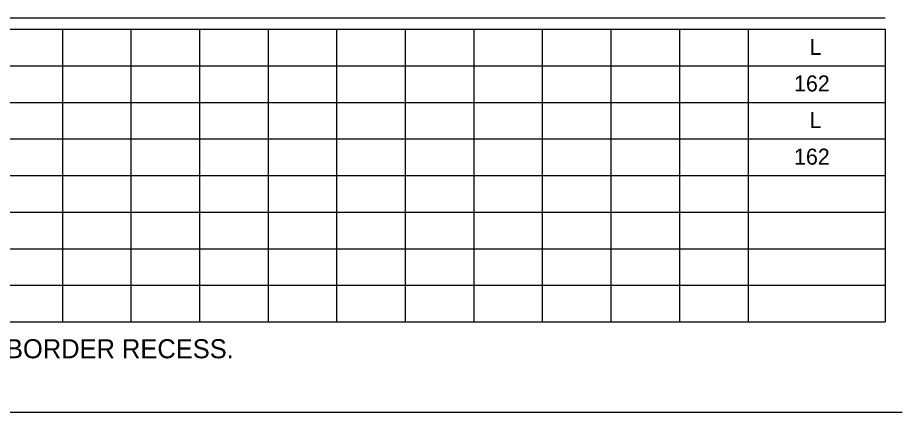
# Model space of a CAD drawing. Extents: x 10268312 to 10268472, y 2142583 to 2142688.
# Drawn here: x 10268433.03 to 10268471.73, y 2142640.28 to 2142657.53 of the extents above; entities that cross this region are included whole.
import ezdxf

# ---------------------------------------------------------------- set-up
doc = ezdxf.new("R2010")
doc.units = 0
for name, color, linetype in [('SheetBorder_dp', 7, 'Continuous'), ('SumBoxLines_dp', 7, 'Continuous'), ('SumBoxLinesMin_dp', 7, 'Continuous'), ('TextLabel', 7, 'Continuous'), ('TextNotes', 7, 'Continuous')]:
    doc.layers.add(name, color=color, linetype=linetype)

msp = doc.modelspace()

# ---------------------------------------------------------------- linework, layer by layer
at = {"layer": 'SheetBorder_dp'}
msp.add_line((10268317.73, 2142640.282), (10268471.73, 2142640.282), dxfattribs=at)
at = {"layer": 'SumBoxLines_dp'}
for p, q in [((10268418.73, 2142657.532), (10268470.98, 2142657.532)), ((10268395.48, 2142657.032), (10268470.98, 2142657.032)), ((10268434.98, 2142657.032), (10268434.98, 2142655.432)), ((10268437.98, 2142657.032), (10268437.98, 2142655.432)), ((10268440.98, 2142657.032), (10268440.98, 2142653.832)), ((10268443.98, 2142657.032), (10268443.98, 2142653.832)), ((10268446.98, 2142657.032), (10268446.98, 2142655.432)), ((10268449.98, 2142657.032), (10268449.98, 2142655.432)), ((10268452.98, 2142657.032), (10268452.98, 2142655.432)), ((10268455.98, 2142657.032), (10268455.98, 2142655.432)), ((10268458.98, 2142657.032), (10268458.98, 2142655.432)), ((10268461.98, 2142657.032), (10268461.98, 2142655.432)), ((10268464.98, 2142657.032), (10268464.98, 2142655.432)), ((10268470.98, 2142657.032), (10268470.98, 2142644.232)), ((10268434.98, 2142655.432), (10268434.98, 2142649.032)), ((10268437.98, 2142655.432), (10268437.98, 2142647.432)), ((10268440.98, 2142655.432), (10268440.98, 2142647.432)), ((10268443.98, 2142655.432), (10268443.98, 2142649.032)), ((10268446.98, 2142655.432), (10268446.98, 2142649.032)), ((10268449.98, 2142655.432), (10268449.98, 2142644.232)), ((10268452.98, 2142655.432), (10268452.98, 2142644.232)), ((10268455.98, 2142655.432), (10268455.98, 2142649.032)), ((10268458.98, 2142655.432), (10268458.98, 2142649.032)), ((10268461.98, 2142655.432), (10268461.98, 2142649.032)), ((10268464.98, 2142655.432), (10268464.98, 2142644.232)), ((10268395.48, 2142653.832), (10268470.98, 2142653.832)), ((10268395.48, 2142650.632), (10268470.98, 2142650.632)), ((10268434.98, 2142649.032), (10268434.98, 2142644.232)), ((10268443.98, 2142649.032), (10268443.98, 2142644.232)), ((10268446.98, 2142649.032), (10268446.98, 2142644.232)), ((10268455.98, 2142649.032), (10268455.98, 2142644.232)), ((10268458.98, 2142649.032), (10268458.98, 2142644.232)), ((10268461.98, 2142649.032), (10268461.98, 2142644.232)), ((10268395.48, 2142647.432), (10268470.98, 2142647.432)), ((10268437.98, 2142647.432), (10268437.98, 2142644.232)), ((10268440.98, 2142647.432), (10268440.98, 2142644.232)), ((10268395.48, 2142644.232), (10268470.98, 2142644.232))]:
    msp.add_line(p, q, dxfattribs=at)
at = {"layer": 'SumBoxLinesMin_dp'}
for p, q in [((10268395.48, 2142655.432), (10268470.98, 2142655.432)), ((10268395.48, 2142652.232), (10268470.98, 2142652.232)), ((10268395.48, 2142649.032), (10268470.98, 2142649.032)), ((10268395.48, 2142645.832), (10268470.98, 2142645.832))]:
    msp.add_line(p, q, dxfattribs=at)

# ---------------------------------------------------------------- texts
at = {"layer": 'TextLabel'}
for s, p in [('L', (10268467.668, 2142655.907)), ('162', (10268466.993, 2142654.307)), ('L', (10268467.668, 2142652.707)), ('162', (10268466.993, 2142651.107))]:
    msp.add_text(s, height=0.7, dxfattribs=at).set_placement(p)
at = {"layer": 'TextNotes'}
msp.add_text('NOTE:  END DIMENSIONS INCLUDE BORDER WIDTH, MARGIN AND BORDER RECESS.  ', height=0.83333, dxfattribs=at).set_placement((10268396.479, 2142642.643))

doc.saveas('drawing.dxf')
